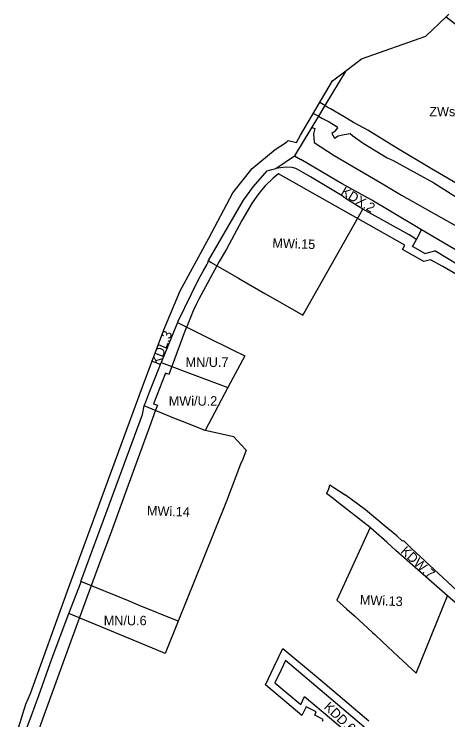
# Model space of a CAD drawing. Extents: x 7418991 to 7423142, y 5547704 to 5549547.
# Drawn here: x 7419425.1 to 7419654.4, y 5548518.9 to 5548891.6 of the extents above; entities that cross this region are included whole.
import ezdxf

# ---------------------------------------------------------------- set-up
doc = ezdxf.new("R2010")
doc.units = 0
for name, color, linetype in [('LIN_Linia Zabudowy Nieprzekraczalna', 7, 'Continuous'), ('LIN_linie_rozgraniczajace', 7, 'Continuous'), ('LIN_Orientacyjny przebieg terenow WS pod terenami komunikacyjnymi', 7, 'Continuous'), ('TXT_Oznaczenia_przeznaczen', 7, 'Continuous')]:
    doc.layers.add(name, color=color, linetype=linetype)

msp = doc.modelspace()

# ---------------------------------------------------------------- linework, layer by layer
at = {"layer": 'LIN_Linia Zabudowy Nieprzekraczalna'}
for points in [[(7419672.29, 5548746.33), (7419651.66, 5548758.24), (7419645.22, 5548761.87), (7419641.66, 5548760.9), (7419630.35, 5548767.34), (7419631.56, 5548769.58), (7419564.85, 5548807.23), (7419562.1, 5548804.93), (7419557.82, 5548800.92), (7419555.06, 5548797.64), (7419553.07, 5548795.03), (7419550.89, 5548791.93), (7419545.39, 5548782.65), (7419537.3, 5548767.5), (7419533.53, 5548760.9), (7419522.82, 5548741.12), (7419521.5, 5548738.65), (7419519.75, 5548734.92), (7419516.54, 5548727), (7419516.35, 5548726.58), (7419515.37, 5548724.15), (7419514.04, 5548720.85), (7419506.83, 5548701.26), (7419505.03, 5548701.96), (7419503.15, 5548697.13), (7419500.64, 5548690.67), (7419498.78, 5548685.84), (7419500.83, 5548685.02), (7419499.86, 5548682.43), (7419496.68, 5548673.62), (7419490.64, 5548657.31), (7419490.64, 5548657.32), (7419484.65, 5548640.83), (7419477.89, 5548622.37), (7419475.77, 5548616.63), (7419470.94, 5548603.66), (7419465.52, 5548588.86), (7419455.09, 5548560.53), (7419455.09, 5548560.54), (7419440, 5548519.24), (7419438.02, 5548513.34)], [(7419588.03, 5548518.15), (7419588.53, 5548519.17), (7419584.05, 5548521.4), (7419584.85, 5548523.18), (7419579.44, 5548525.74), (7419577.16, 5548521.27), (7419557.9, 5548537.48), (7419562.64, 5548547.11), (7419567.08, 5548556.57), (7419584.88, 5548541.74), (7419598.69, 5548530.09), (7419612.57, 5548518.33)]]:
    msp.add_lwpolyline(points, dxfattribs=at)
at = {"layer": 'LIN_linie_rozgraniczajace'}
for p, q in [((7419582.4, 5548831.75), (7419584.01, 5548831.19)), ((7419584.01, 5548831.19), (7419583.43, 5548828.35)), ((7419583.43, 5548828.35), (7419583.79, 5548823.75)), ((7419583.79, 5548823.75), (7419594.34, 5548816.95)), ((7419594.34, 5548816.95), (7419619.33, 5548802.29)), ((7419619.33, 5548802.29), (7419629.93, 5548795.98)), ((7419629.93, 5548795.98), (7419664.13, 5548776.68)), ((7419642.2, 5548765.19), (7419635.73, 5548768.88)), ((7419642.2, 5548765.19), (7419647.49, 5548766.65))]:
    msp.add_line(p, q, dxfattribs=at)
for points in [[(7419425.07, 5548507.35), (7419431.26, 5548527.19), (7419433.76, 5548532.77), (7419453.34, 5548587.08), (7419492.41, 5548693.42), (7419504.2, 5548724.91), (7419512.9, 5548745.44), (7419527.95, 5548773.25), (7419540.7, 5548797.26), (7419551, 5548810.13), (7419563.12, 5548820.05), (7419569.05, 5548823.96), (7419569.88, 5548824.84), (7419574.32, 5548823.89), (7419576.4, 5548827.61), (7419593.35, 5548856.34), (7419600.45, 5548861.71), (7419604.8, 5548865.01), (7419608.79, 5548868.04), (7419642.73, 5548879.91), (7419653.46, 5548890.27), (7419654.85, 5548891.62)], [(7419653.46, 5548890.27), (7419657.38, 5548887.2), (7419663.34, 5548882.63), (7419668.24, 5548878.71), (7419669.69, 5548879.5), (7419671.68, 5548878.12), (7419673.38, 5548876.24), (7419674.6, 5548874.55), (7419681.66, 5548865.01)], [(7419600.45, 5548861.71), (7419589.36, 5548843.31), (7419585.97, 5548837.67), (7419573.36, 5548816.74)], [(7419590.61, 5548842.54), (7419589.36, 5548843.31)], [(7419672.39, 5548793.99), (7419670.45, 5548795.12), (7419663.47, 5548799.57), (7419645.7, 5548809.82), (7419626.86, 5548821.22), (7419612.15, 5548830.31), (7419604.5, 5548834.35), (7419599.55, 5548837.33), (7419592.42, 5548841.53), (7419590.61, 5548842.54)], [(7419585.97, 5548837.67), (7419587.81, 5548836.7), (7419591.6, 5548834.68), (7419595.3, 5548832.46), (7419595.97, 5548831.61), (7419594.69, 5548829.88)], [(7419594.69, 5548829.88), (7419594.78, 5548829.74), (7419593.03, 5548828.62), (7419594.52, 5548826.08), (7419596.36, 5548827.28)], [(7419596.36, 5548827.28), (7419599.62, 5548828.03), (7419602.7, 5548828.58), (7419604.18, 5548827.38), (7419609.56, 5548823.44)], [(7419609.56, 5548823.44), (7419622.25, 5548815.75), (7419625.5, 5548814.25)], [(7419511.62, 5548729.16), (7419522.6, 5548751.45), (7419525.08, 5548755.86), (7419526.9, 5548759.25), (7419527.49, 5548760.24), (7419527.78, 5548761.48), (7419546.39, 5548793.38), (7419551.63, 5548800.64), (7419558.84, 5548808.81), (7419561.33, 5548809.61), (7419563.37, 5548810.03), (7419573.36, 5548816.74)], [(7419573.36, 5548816.74), (7419576.68, 5548814.79)], [(7419598.54, 5548801.94), (7419595.12, 5548803.97), (7419576.68, 5548814.79)], [(7419625.5, 5548814.25), (7419646.9, 5548802.53), (7419670.62, 5548787.47), (7419688.23, 5548776.78), (7419703.95, 5548767.79), (7419722.74, 5548757.55), (7419726.03, 5548754.45), (7419747.43, 5548740.85), (7419763.5, 5548730.15), (7419780.13, 5548715.88), (7419792.86, 5548704.27), (7419808.71, 5548688.73), (7419820.43, 5548677.88), (7419853.39, 5548642.59), (7419872.11, 5548623.4), (7419886.03, 5548610.8), (7419931.98, 5548578.77), (7419945.38, 5548570.24), (7419972.32, 5548556.78), (7419994.74, 5548547.57), (7420013.19, 5548540.38), (7420039.08, 5548532.71)], [(7419637.77, 5548772.62), (7419633.89, 5548775.03), (7419609.47, 5548788.67), (7419600.22, 5548794.26), (7419598.48, 5548795.67), (7419581.77, 5548805.75), (7419575.88, 5548808.95), (7419574.02, 5548810.1), (7419571.99, 5548810.66), (7419568.63, 5548810.73), (7419563.37, 5548810.03)], [(7419640.53, 5548777.71), (7419624.22, 5548787.32), (7419614.16, 5548793.28), (7419598.54, 5548801.94)], [(7419527.78, 5548761.48), (7419529.23, 5548760.4), (7419543.7, 5548752.13), (7419545.38, 5548751.17), (7419557.69, 5548744.13), (7419568.23, 5548738.11), (7419577.74, 5548732.68), (7419578.18, 5548733.46), (7419609.47, 5548788.67)], [(7419635.73, 5548768.88), (7419637.77, 5548772.62), (7419640.53, 5548777.71)], [(7419784.8, 5548679.24), (7419769.44, 5548694.15), (7419759.49, 5548702.88), (7419736.73, 5548718.74), (7419720.21, 5548729.84), (7419697.28, 5548744.04), (7419677.6, 5548755.76), (7419657.58, 5548767.66), (7419640.53, 5548777.71)], [(7419728.96, 5548715.51), (7419720.27, 5548722.23), (7419717.94, 5548723.83), (7419710.46, 5548729.13), (7419693.47, 5548739.11), (7419691.92, 5548740.02), (7419685.6, 5548743.73), (7419677.45, 5548748.53), (7419666.76, 5548755), (7419647.49, 5548766.65)], [(7419511.62, 5548729.16), (7419511.49, 5548728.84), (7419502.89, 5548707.68)], [(7419511.49, 5548728.84), (7419526.31, 5548721.44), (7419540.49, 5548714.37), (7419546.97, 5548711.14), (7419538.07, 5548694.41)], [(7419429.32, 5548507.99), (7419434.22, 5548521.2), (7419438.12, 5548531.83), (7419444.94, 5548551.05), (7419446.77, 5548555.96), (7419454.08, 5548574.99), (7419454.09, 5548575.01), (7419460.53, 5548591.77), (7419460.36, 5548592.03), (7419472.32, 5548624.39), (7419492.93, 5548680.12), (7419493.76, 5548684.74), (7419493.78, 5548684.78), (7419494.64, 5548686.9), (7419496.88, 5548692.56), (7419501.82, 5548704.89), (7419502.89, 5548707.68)], [(7419502.89, 5548707.68), (7419523.43, 5548699.93), (7419538.07, 5548694.41), (7419526.01, 5548671.73)], [(7419547.73, 5548661.39), (7419545.08, 5548664.21), (7419541.31, 5548668.3), (7419526.01, 5548671.73), (7419514.03, 5548676.5), (7419509.56, 5548678.28), (7419493.78, 5548684.78)], [(7419547.73, 5548661.39), (7419545.96, 5548656.66), (7419544.83, 5548653.89), (7419537.33, 5548634.46), (7419525.11, 5548603.81), (7419511.83, 5548570.99), (7419490.91, 5548579.54), (7419485.54, 5548581.74), (7419460.36, 5548592.03)], [(7419591.24, 5548640.35), (7419591.99, 5548642.84), (7419592.06, 5548643.07), (7419594.17, 5548641.67), (7419600.03, 5548637.69)], [(7419593.79, 5548635.76), (7419590.27, 5548638.38), (7419591.24, 5548640.35)], [(7419671.78, 5548569.04), (7419654.18, 5548584.43), (7419634.31, 5548601.81), (7419626.95, 5548608.32), (7419622.06, 5548612.67), (7419617.81, 5548616.49), (7419613.48, 5548620.31), (7419613.36, 5548620.41), (7419601.41, 5548629.83), (7419597.43, 5548632.85), (7419593.79, 5548635.76)], [(7419673.74, 5548573.64), (7419634.95, 5548609.61), (7419631.03, 5548613.4), (7419630.33, 5548613.28), (7419627.38, 5548616.03), (7419620.71, 5548621.63), (7419610.91, 5548629.87), (7419600.03, 5548637.69)], [(7419613.36, 5548620.41), (7419603.7, 5548599.41), (7419595.74, 5548582.06), (7419601, 5548577.4), (7419605.05, 5548573.81), (7419614.51, 5548565.04), (7419615.69, 5548563.95), (7419619.79, 5548560.14), (7419628.16, 5548552.38), (7419637.6, 5548543.62), (7419654.18, 5548584.43)], [(7419511.83, 5548570.99), (7419504.98, 5548553.9), (7419500.27, 5548555.86), (7419454.09, 5548575.01)], [(7419640.05, 5548492.21), (7419624.7, 5548502.82), (7419609.99, 5548515.28), (7419596.11, 5548527.03), (7419582.31, 5548538.67), (7419568.5, 5548550.18), (7419566.25, 5548545.38), (7419562.87, 5548538.52), (7419576.59, 5548526.98), (7419578.67, 5548531.3), (7419592.9, 5548519.28), (7419607.01, 5548507.32), (7419621.38, 5548495.08), (7419636.83, 5548484.45)]]:
    msp.add_lwpolyline(points, dxfattribs=at)
at = {"layer": 'LIN_Orientacyjny przebieg terenow WS pod terenami komunikacyjnymi'}
msp.add_line((7419589.36, 5548843.31), (7419586.64, 5548844.97), dxfattribs=at)
msp.add_lwpolyline([(7419585.97, 5548837.67), (7419583.21, 5548839.16)], dxfattribs=at)

# ---------------------------------------------------------------- texts
at = {"layer": 'TXT_Oznaczenia_przeznaczen'}
for s, p in [('ZWs/ZZ.3', (7419644.58, 5548837.65)), ('MN/U.7', (7419515.74, 5548705.29)), ('MWi/U.2', (7419506.83, 5548684.83)), ('MN/U.6', (7419472.48, 5548568.85))]:
    msp.add_text(s, height=5, dxfattribs=at).set_placement(p)
for s, rotation, p in [('KDX.2', 329.0084, (7419597.38, 5548796.54)), ('MWi.15', 357.9964, (7419561.55, 5548768.3)), ('KDL.3', 68.3528, (7419501.93, 5548705.87)), ('MWi.14', 357.9964, (7419495.23, 5548626.96)), ('KDW.7', 317.646, (7419629.05, 5548607.4)), ('MWi.13', 357.6291, (7419607.78, 5548579.85)), ('KDD.6', 316.2383, (7419588.48, 5548525.25))]:
    msp.add_text(s, height=5, rotation=rotation, dxfattribs=at).set_placement(p)

doc.saveas('drawing.dxf')
